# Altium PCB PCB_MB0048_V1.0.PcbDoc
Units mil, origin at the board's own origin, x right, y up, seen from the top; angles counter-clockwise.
Board outline 787.4 x 3937.01 mil, 2 copper layers (Top Layer, Bottom Layer); 26 components, 25 nets, 64 pads, 11 vias.
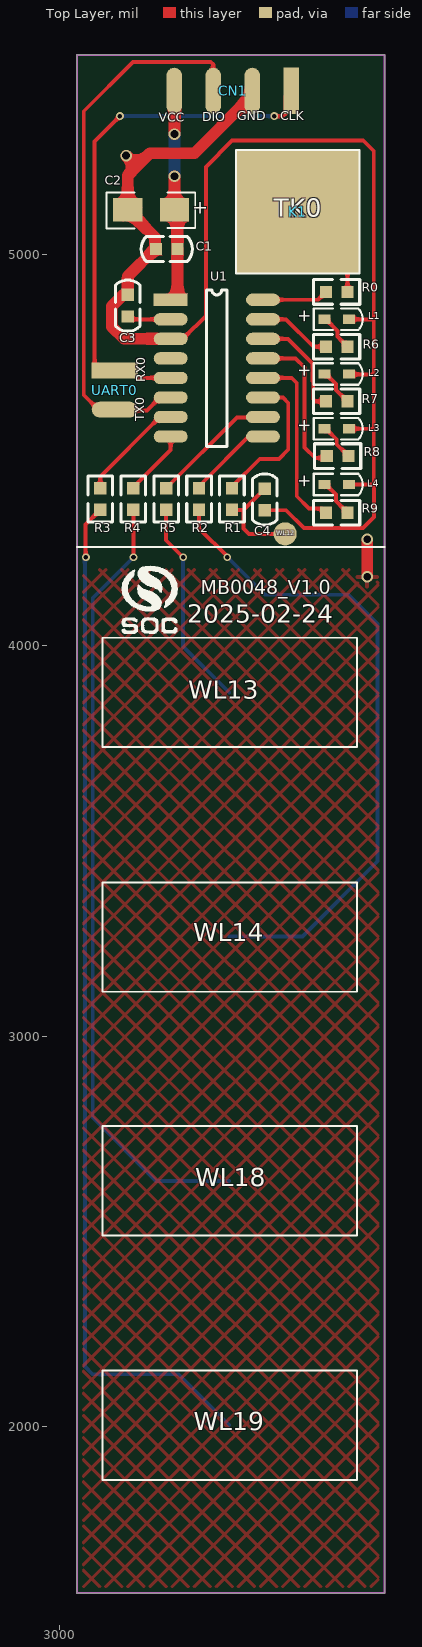
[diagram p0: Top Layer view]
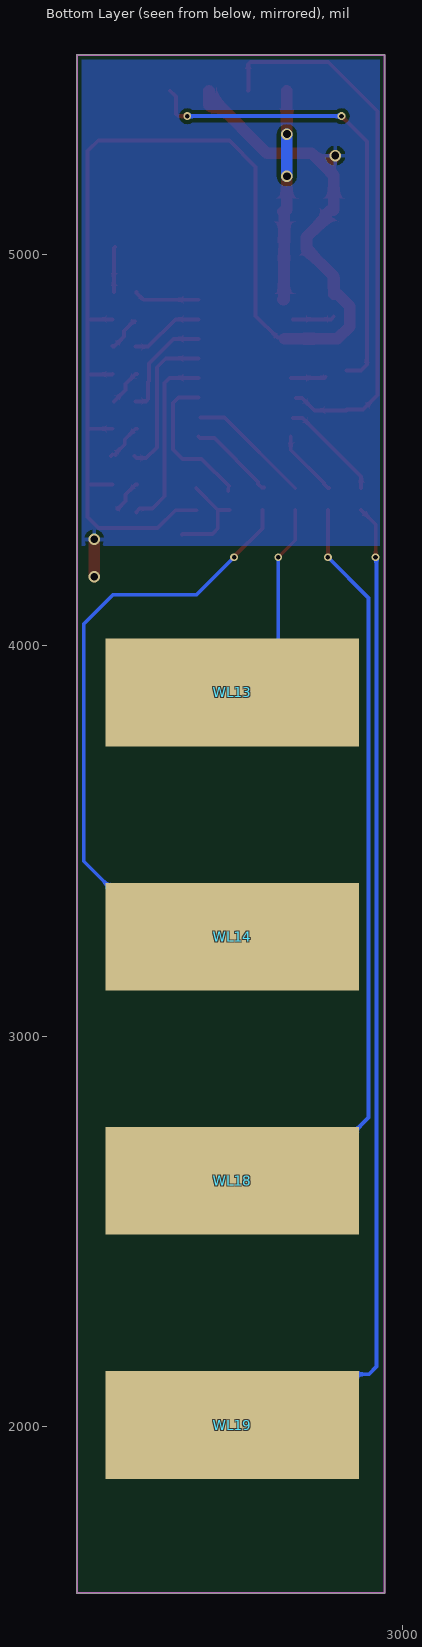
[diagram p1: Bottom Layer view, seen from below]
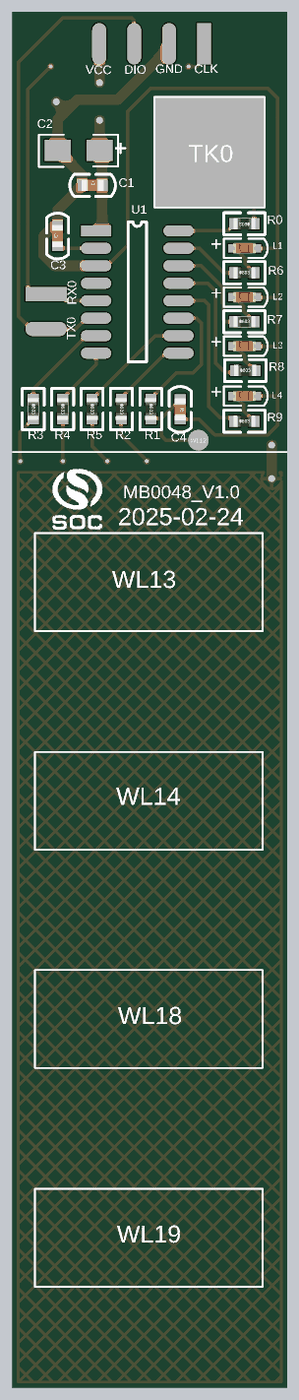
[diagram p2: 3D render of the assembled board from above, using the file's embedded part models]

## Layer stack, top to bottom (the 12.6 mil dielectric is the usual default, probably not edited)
Top Solder: solder mask 0.4, Solder Resist, Dk 3.5
Top Layer: signal copper 1.4
Dielectric 1: dielectric 12.6, FR-4, Dk 4.8
Bottom Layer: signal copper 1.4
Bottom Solder: solder mask 0.4, Solder Resist, Dk 3.5

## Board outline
3045,1574.8 3045,5511.81 3832.4,5511.81 3832.4,1574.8

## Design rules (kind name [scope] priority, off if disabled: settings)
Clearance [All] p1: gap=10 ignorepadtopadclearanceinfootprint=FALSE except(0: Arc-Hole Track-Hole SMDPad-Hole THPad-Hole Via-Hole Fill-Hole Poly-Hole Region-Hole Text-Hole)
PolygonConnect [All] p1: connectstyle=Relief reliefconductorwidth=10 reliefentries=4 polygonreliefangle="90 Angle" airgapwidth=10
RoutingVias [All] p1: holewidth=28 width=50 viastyle="Through Hole" minholewidth=28 minwidth=50 maxholewidth=28 maxwidth=50
SolderMaskExpansion [All] p1: expansion=4 istentingtop=FALSE
Width [All] p1: maxlimit=30 minlimit=10 preferedwidth=10
30 further rules are at their usual default settings.

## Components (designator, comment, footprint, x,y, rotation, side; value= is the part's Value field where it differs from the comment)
C1 "104" C0603-SMT 3275,5015 r0 top
C2 "A/10uF/16V" A-3216 3295,5115 r180 top
C3 "103" C0603-SMT 3175,4870 r90 top
C4 "15pf" C0603-SMT 3526,4374 r270 top
CN1 "CN4" HDR2.54-WS-4P 3444,5361.26 r180 top
K1 "K-QM" KEY-WL38-2 3610,5110 r0 top
L1 "LED" LED-0603-SMT 3710,4835 r0 top
L2 "LED" LED-0603-SMT 3710,4695 r0 top
L3 "LED" LED-0603-SMT 3710,4555 r0 top
L4 "LED" LED-0603-SMT 3710,4412 r0 top
R0 "510R" R0603-SMT 3710,4905 r180 top
R1 "510R" R0603-SMT 3441.8,4375 r270 top
R2 "510R" R0603-SMT 3357.6,4375 r270 top
R3 "510R" R0603-SMT 3105,4375 r270 top
R4 "510R" R0603-SMT 3189.2,4375 r270 top
R5 "510R" R0603-SMT 3273.4,4375 r270 top
R6 "5.1K" R0603-SMT 3710,4765 r0 top
R7 "5.1K" R0603-SMT 3710,4625 r0 top
R8 "5.1K" R0603-SMT 3712.44,4485 r0 top
R9 "5.1K" R0603-SMT 3710,4340 r0 top
U1 "SC92F8481" SOP16 3285,4885 r0 top
UART0 "CON1*2" HDR2.54-WS-2P 3205.74,4654 r270 top
WL13 "K-QM" KEY-WL38-1 3435,3880 r0 top (schematic designator K5)
WL14 "K-QM" KEY-WL38-1 3435,3255 r0 top (schematic designator K2)
WL18 "K-QM" KEY-WL38-1 3435,2630 r180 top (schematic designator K4)
WL19 "K-QM" KEY-WL38-1 3435,2005 r180 top (schematic designator K3)

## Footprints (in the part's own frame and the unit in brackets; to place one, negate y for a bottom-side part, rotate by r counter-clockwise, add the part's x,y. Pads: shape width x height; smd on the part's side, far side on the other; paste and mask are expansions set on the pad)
A-3216 [mil]
  rect 75x60 smd: 1(0,0) 2(120,0)
  silkscreen extent -53,-45 174,47
C0603-SMT [mm]
  rect 0.8x0.8 smd: 1(-0.7,0) 2(0.7,0)
  silkscreen extent -1.66,-0.8 1.66,0.8, body extent -0.8,-0.4 0.8,0.4, height 0.3
HDR2.54-WS-2P [mm] "2P卧式贴片排针2.54"
  rect 1.02x3 smd: 1(-1.27,-1.619)
  oval 1.02x3 smd: 2(1.27,-1.619)
HDR2.54-WS-4P [mm] "4P卧式贴片排针2.54"
  rect 1.02x3 smd: 1(-3.81,-1.492)
  oval 1.02x3 smd: 2(-1.27,-1.492) 3(1.27,-1.492) 4(3.81,-1.492)
KEY-WL38-1 [mm]
  rect 16.5x7 smd far side mask+0.102: 1(0,0)
KEY-WL38-2 [mm]
  rect 8x8 smd mask+0.102: 1(0,0)
LED-0603-SMT [mm]
  rect 0.8x0.6 smd: A(-0.8,0) K(0.8,0)
  silkscreen extent -1.5,-0.7 1.69,0.7, body extent -0.81,-0.4 0.81,0.4, height 0.6
R0603-SMT [mm]
  rect 0.8x0.8 smd: 1(-0.7,0) 2(0.7,0)
  silkscreen extent -1.5,-0.8 1.5,0.8, body extent -0.8,-0.41 0.8,0.41, height 0.45
SOP16 [mm]
  rect 2.2x0.8 smd: 1(0,0)
  oval 2.2x0.8 smd: 2(0,-1.27) 3(0,-2.54) 4(0,-3.81) 5(0,-5.08) 6(0,-6.35) 7(0,-7.62) 8(0,-8.89) 9(6,-8.89) 10(6,-7.62) 11(6,-6.35) 12(6,-5.08) 13(6,-3.81) 14(6,-2.54) 15(6,-1.27) 16(6,0)
  silkscreen extent 2.33,-9.53 3.67,0.64

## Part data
C1: library part C_3, "C"
C2: library part T-A/10uF/16V
C3 C4: library part C_1, "C"
CN1: "4P-SOCKET"
R0 R1 R2 R3 R4 R5 R6 R7 R8 R9: library part R, "RES"
U1: "电压:2.4V-5.5V;ROM:128KB;RAM:256B+8KB;32/16/8/4MHz"

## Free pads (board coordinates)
  round 59.06 smd mask+4: 2(3578,4286)

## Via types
v1: diameter 20, hole 12, Top Layer to Bottom Layer, tented both sides, 6 vias
v2: diameter 30, hole 20, Top Layer to Bottom Layer, tented both sides, 5 vias

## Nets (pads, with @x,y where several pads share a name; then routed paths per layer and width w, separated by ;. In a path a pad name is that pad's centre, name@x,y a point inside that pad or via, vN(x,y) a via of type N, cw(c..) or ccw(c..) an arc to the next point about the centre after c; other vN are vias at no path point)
CLK: CN1.1 U1.5 UART0.1 | length 1302.9
  Top Layer w10: UART0.1 3105.44,4704 3090.37,4719.08 3090.37,4732.71 3090,4733.08 3090,5290 v1(3155,5355) ; UART0.1@3196,4688 3199,4685 U1.5 ; v1(3550,5355) 3573.06,5355 3578.92,5360.86 3578.92,5404.92 CN1.1
  Bottom Layer w10: v1(3155,5355) v1(3550,5355)
DIO: CN1.3 U1.6 UART0.2 | length 1418.5
  Top Layer w10: UART0.2@3142,4602 3224.44,4602 3256.44,4634 U1.6@3272,4634 ; UART0.2 3100,4604 3062.5,4641.5 3062.5,5367.5 3189,5494 3279.41,5494 3279.47,5494.06 3387.64,5494.06 3393.56,5488.14 3393.56,5420.44 CN1.3
GND: C1.1 C2.2 C3.2 C4.2 CN1.2 L1.K L2.K L3.K L4.K U1.3 | length 3653.8
  Top Layer w10: U1.3@3302,4788 3319,4788 3375,4844 3375,5225.32 3442.16,5292.48 3777.84,5292.48 3804.9,5265.41 3804.9,4694 3804.9,4550 3804.9,4412 L4.K ; C4.2 3580.53,4346.44 3625.97,4301 3777,4301 3805,4329 3805,4412 ; L3.K 3799,4555 3804,4550 ; L2.K 3741.5,4694.75 3742.24,4694 3800,4694 ; L1.K 3801,4835 3802,4836
  Top Layer w30: v2(3171,5254) 3198.5,5226.5 ; C1.1@3245,5015 3175,4945 3175,4899 3164.71,4899 3134.25,4868.54 3134.25,4816.34 3165.59,4785 U1.3 U1.3@3302,4785 ; C1.1@3245,5020 3245,5045 3197.5,5092.5 3197.5,5100 3182.5,5115 C2.2 3175,5203 3198.5,5226.5 ; CN1.2@3486,5394 3480,5394 3346,5260 3232,5260 3198.5,5226.5 ; CN1.2@3489.31,5379.08 3494,5383.77 CN1.2 ; v2(3788,4176) v2@3788,4270
  other v2: 3788,4272
NetC3_1: C3.1 U1.2 | length 108.1
  Top Layer w10: C3.1 3182.44,4835 U1.2@3280,4835
NetC4_1: C4.1 pad.2 R1.2 | length 254.2
  Top Layer w10: R1.2 3471.88,4347.44 ; C4.1@3527,4403 3527,4402.56 C4.1 3471.88,4347.44 ; pad.2@3563,4284 3561,4286 3485,4286 3471.88,4299.12 3471.88,4347.44
NetK1_1: K1.1 R0.1 | length 116.1
  Top Layer w10: K1.1@3735,5020 3737.56,5017.44 R0.1
NetK2_1: R2.2 WL14.1 | length 1675.1
  Top Layer w10: R2.2 3357.6,4300.11 3430,4227.71 v1@3430,4225
  Bottom Layer w10: v1(3430,4226) 3526,4130 3740,4130 3814.9,4055.1 3814.9,3447.89 3622.01,3255 WL14.1
NetK3_1: R3.2 WL19.1 | length 2641.1
  Top Layer w10: v1(3068,4226) 3067.5,4226.5 3067.5,4309.94 R3.2
  Bottom Layer w10: v1(3068,4226) 3066.09,4224.09 3066.09,4217.02 3065.59,4216.52 3065.59,2154.41 3085,2135 3305,2135 WL19.1
NetK4_1: R4.2 WL18.1 | length 2018.3
  Top Layer w10: R4.2 3190,4346.64 v1@3190,4223
  Bottom Layer w10: v1(3190,4226) 3085.59,4121.59 3085.59,2792.41 3247.99,2630 WL18.1
NetK5_1: R5.2 WL13.1 | length 534.4
  Top Layer w10: R5.2 3273.4,4269.6 v1(3317,4226)
  Bottom Layer w10: v1(3317,4226) 3317,3998 WL13.1
NetL1_A: L1.A R6.2 | length 91.3
  Top Layer w10: L1.A@3684,4830 3687.44,4830 3712,4805.44 3712,4790.56 R6.2 ; R6.2@3740,4765 R6.2@3741.5,4766.5
NetL2_A: L2.A R7.2 | length 96.8
  Top Layer w10: L2.A 3682.44,4695 3708,4669.44 3708,4654.56 R7.2
NetL3_A: L3.A R8.2 | length 97.2
  Top Layer w10: L3.A 3682.44,4555 3710,4527.44 3710,4515 3734,4491 R8.2@3734,4488 ; R8.2@3741.5,4488.5 R8.2@3745,4485
NetL4_A: L4.A R9.2 | length 85.1
  Top Layer w10: L4.A 3682.44,4412 3708,4386.44 3708,4369.56 3727.56,4350 R9.2@3728,4350
NetR0_2: R0.2 U1.16 | length 168.5
  Top Layer w10: U1.16 3662.44,4885 3680,4902.56 R0.2@3680,4905
NetR1_1: R1.1 U1.11 | length 379.1
  Top Layer w10: R1.1@3443,4408 3513,4478 3562,4478 3586,4502 3586,4621 3572.13,4634.87 3521.35,4634.87 U1.11 ; R1.1@3445,4395 R1.1@3445,4402.56
NetR2_1: R2.1 U1.9 | length 224.5
  Top Layer w10: R2.1@3354,4404.22 3359.26,4404.22 3368.35,4413.31 3368.35,4418.57 3480.67,4530.89 3517.11,4530.89 U1.9
NetR3_1: R3.1 U1.7 | length 266.9
  Top Layer w10: R3.1 3105,4432.56 3254.44,4582 U1.7@3280,4582
NetR4_1: R4.1 U1.8 | length 174.3
  Top Layer w10: R4.1@3186.92,4402.92 3189.56,4402.92 3199.95,4413.31 3199.95,4415.95 3285,4501 U1.8
NetR5_1: R5.1 U1.10 | length 317.9
  Top Layer w10: R5.1 3454.93,4584.09 U1.10@3516.09,4584.09
NetR6_1: R6.1 U1.15 | length 190.2
  Top Layer w10: U1.15 3580,4835 3650,4765 R6.1
NetR7_1: R7.1 U1.14 | length 279.7
  Top Layer w10: U1.14 3585,4785 3647.76,4722.24 3647.76,4676.98 3650,4674.73 3650,4630.86 3655.86,4625 R7.1
NetR8_1: R8.1 U1.13 | length 391.6
  Top Layer w10: U1.13 3605,4735 3627.76,4712.24 3627.76,4507.24 3655,4480 3680,4480 R8.1@3685,4485
NetR9_1: R9.1 U1.12 | length 473
  Top Layer w10: U1.12 3595,4685 3607.76,4672.24 3607.76,4382.24 3639.25,4350.75 3671.69,4350.75 3680,4342.44 R9.1@3680,4340
VCC: C1.2 C2.1 CN1.4 U1.1 | length 533.6
  Top Layer w30: C2.1 v2(3295,5201) ; v2(3295,5309) CN1.4@3295,5420 ; U1.1@3305,4885 3303.31,4885 3302.56,4885.75 C1.2 3301.81,5015.75 3301.81,5106.81 C2.1@3305,5110
  Bottom Layer w30: v2(3295,5201) v2(3295,5309)
pads on no net: U1.4

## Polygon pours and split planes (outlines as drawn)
GND on Bottom Layer "GND_L02_P005" (solid, remove dead copper, pour order 5): 3046,5510 3047,5509 3047,4255 3831,4255 3832,4256 3830,4258 3830,5510 3045,5510
GND on Top Layer "GND_L01_P000" (hatched 45Degree grid 40 track 8, pour order 0): 3817,4194 3817,1593 3820,1590 3812,1582 3055,1582 3055,4194

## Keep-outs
Keep-Out Layer:
  the board outline again, w5

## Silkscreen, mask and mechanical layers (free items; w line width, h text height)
Top Overlay:
  drawing of 26 lines, arcs and shapes, not listed
  text "GND" at 3455,5336.43 h40
  text "CLK" at 3566,5336.43 h40
  text "DIO" at 3366,5334.43 h40
  text "VCC" at 3255,5333.43 h40
  text "TK0" at 3549,5081.85 h80
  text "RX0" at 3227.57,4674 h40 r90
  text "TX0" at 3225.57,4574 h40 r90
  text "WL12" at 3555,4279 h20
  text "MB0048_V1.0" at 3362,4119.69 h60
  text "2025-02-24" at 3328,4043 h80
Mechanical 1:
  the board outline again, w5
